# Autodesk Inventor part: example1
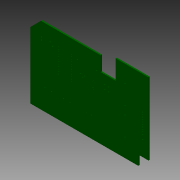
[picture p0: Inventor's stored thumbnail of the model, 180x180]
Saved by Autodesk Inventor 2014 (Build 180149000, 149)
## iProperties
Shininess: 64.0
Length Units: 11272
Angle Units: 11279
Time Units: 11290
Mass Units: 11286
Length Display Precision: 3
Angle Display Precision: 2
Compacted: True
Part Number: example1
Document SubType Name: Modeling
Created: 2003-04
Designer: t_enrig
Manufacturer: Standard
Standards Organization: Custom
Density: 1 g/cm^3
Mass: 18.8046 g
Surface Area: 257.234 cm^2
Volume: 18.8046 cm^3
Material: Generic
Appearance: TranslatedColorStyle
Density: 0.0
Volumn: 0.0
Area: 0.0
PropertySet Name: Model Information
Control State: 0
Master: False
Checked Out: False
Author: t_enrig
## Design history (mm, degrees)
feature "Base1"
body "Solid1"
